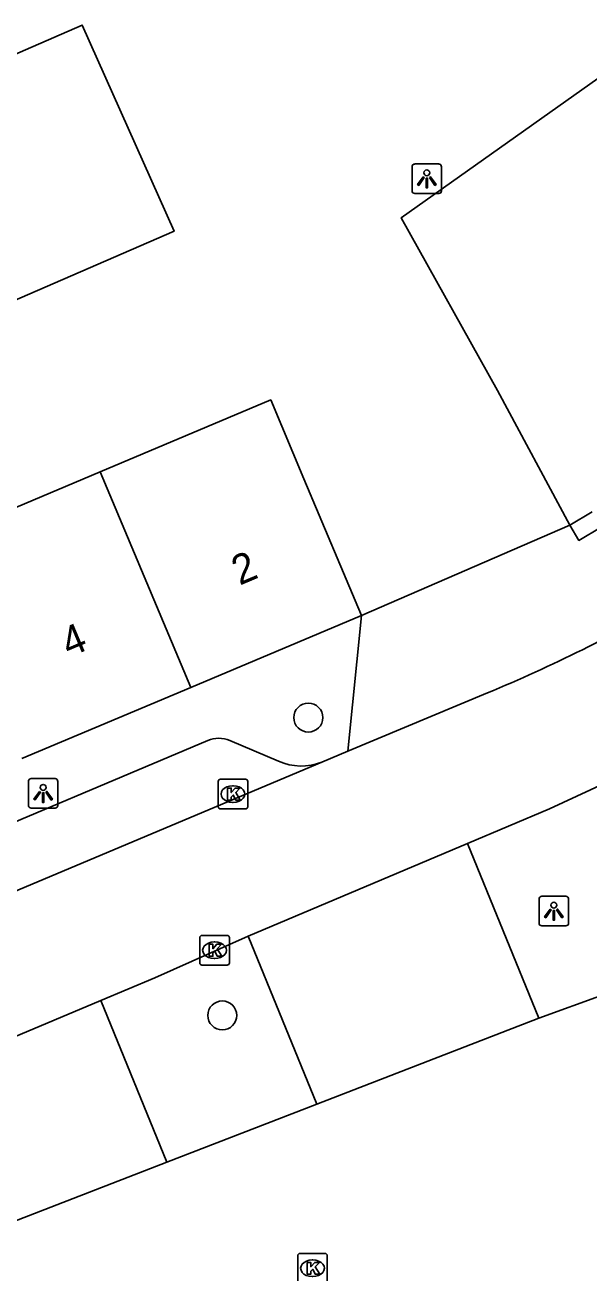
# Model space of a CAD drawing. Extents: x 159888 to 160757, y 384031 to 384746.
# Drawn here: x 160410.46 to 160429.51, y 384536.72 to 384579.11 of the extents above; entities that cross this region are included whole.
import ezdxf

# ---------------------------------------------------------------- set-up
doc = ezdxf.new("R2010")
doc.units = 0
for name, color, linetype in [('IMGEO_Boom', 7, 'Continuous'), ('IMGEO_Kolk', 7, 'Continuous'), ('IMGEO_Lichtpunt', 7, 'Continuous'), ('IMGEO_Pand', 7, 'Continuous'), ('IMGEO_Pand_nummerreeks', 7, 'Continuous'), ('IMGEO_Rijbaan_lokaal_open', 7, 'Continuous'), ('IMGEO_Voetpad_open', 7, 'Continuous')]:
    doc.layers.add(name, color=color, linetype=linetype)

msp = doc.modelspace()

# ---------------------------------------------------------------- linework, layer by layer
at = {"layer": 'IMGEO_Boom'}
for centre in [(160420.029, 384555.732), (160417.123, 384545.68)]:
    msp.add_circle(centre, 0.489, dxfattribs=at)
at = {"layer": 'IMGEO_Kolk'}
for p, q in [((160416.982, 384552.724), (160416.982, 384553.576)), ((160417.057, 384553.65), (160417.909, 384553.65)), ((160417.47, 384553.43), (160417.495, 384553.43)), ((160417.983, 384553.576), (160417.983, 384552.724)), ((160417.909, 384552.65), (160417.057, 384552.65)), ((160417.493, 384552.87), (160417.468, 384552.87)), ((160416.359, 384547.452), (160416.359, 384548.304)), ((160416.434, 384548.378), (160417.286, 384548.378)), ((160417.36, 384548.304), (160417.36, 384547.452)), ((160416.847, 384548.158), (160416.872, 384548.158)), ((160416.87, 384547.598), (160416.845, 384547.598)), ((160417.286, 384547.378), (160416.434, 384547.378)), ((160419.744, 384537.643), (160420.596, 384537.643)), ((160419.669, 384536.717), (160419.669, 384537.569)), ((160420.157, 384537.423), (160420.182, 384537.423)), ((160420.67, 384537.569), (160420.67, 384536.717)), ((160420.18, 384536.863), (160420.155, 384536.863))]:
    msp.add_line(p, q, dxfattribs=at)
for points in [[(160416.982, 384552.724), (160416.982, 384553.576)], [(160417.057, 384553.65), (160417.909, 384553.65)], [(160417.303, 384553.35), (160417.426, 384553.35), (160417.426, 384553.199), (160417.556, 384553.35), (160417.72, 384553.35), (160417.574, 384553.199), (160417.727, 384552.95), (160417.575, 384552.95), (160417.49, 384553.114), (160417.426, 384553.047), (160417.426, 384552.95), (160417.303, 384552.95), (160417.303, 384553.35)], [(160417.983, 384553.576), (160417.983, 384552.724)], [(160417.909, 384552.65), (160417.057, 384552.65)], [(160416.359, 384547.452), (160416.359, 384548.304)], [(160416.434, 384548.378), (160417.286, 384548.378)], [(160417.36, 384548.304), (160417.36, 384547.452)], [(160416.68, 384548.078), (160416.803, 384548.078), (160416.803, 384547.927), (160416.933, 384548.078), (160417.097, 384548.078), (160416.951, 384547.927), (160417.104, 384547.678), (160416.952, 384547.678), (160416.867, 384547.842), (160416.803, 384547.775), (160416.803, 384547.678), (160416.68, 384547.678), (160416.68, 384548.078)], [(160417.286, 384547.378), (160416.434, 384547.378)], [(160419.744, 384537.643), (160420.596, 384537.643)], [(160419.669, 384536.717), (160419.669, 384537.569)], [(160419.99, 384537.343), (160420.113, 384537.343), (160420.113, 384537.192), (160420.243, 384537.343), (160420.407, 384537.343), (160420.261, 384537.192), (160420.414, 384536.943), (160420.262, 384536.943), (160420.177, 384537.107), (160420.113, 384537.04), (160420.113, 384536.943), (160419.99, 384536.943), (160419.99, 384537.343)], [(160420.67, 384537.569), (160420.67, 384536.717)]]:
    msp.add_lwpolyline(points, dxfattribs=at)
for centre, start, end in [((160417.059, 384553.574), 91.552, 178.448), ((160417.059, 384553.574), 91.552, 178.448), ((160417.907, 384553.574), 1.552, 88.448), ((160417.907, 384553.574), 1.552, 88.448), ((160417.059, 384552.726), 181.552, 268.448), ((160417.059, 384552.726), 181.552, 268.448), ((160417.907, 384552.726), 271.552, 358.448), ((160417.907, 384552.726), 271.552, 358.448), ((160416.436, 384548.302), 91.552, 178.448), ((160416.436, 384548.302), 91.552, 178.448), ((160417.284, 384548.302), 1.552, 88.448), ((160417.284, 384548.302), 1.552, 88.448), ((160416.436, 384547.454), 181.552, 268.448), ((160416.436, 384547.454), 181.552, 268.448), ((160417.284, 384547.454), 271.552, 358.448), ((160417.284, 384547.454), 271.552, 358.448), ((160419.746, 384537.567), 91.552, 178.448), ((160419.746, 384537.567), 91.552, 178.448), ((160420.594, 384537.567), 1.552, 88.448), ((160420.594, 384537.567), 1.552, 88.448)]:
    msp.add_arc(centre, 0.0765, start, end, dxfattribs=at)
for centre, major_axis, ratio, start_param, end_param in [((160417.469, 384553.15), (-0.387, 0.002), 0.722429, 4.712389, 7.853982), ((160417.494, 384553.15), (-0.39, 0.002), 0.717154, 1.570796, 4.712389), ((160416.846, 384547.878), (-0.387, 0.002), 0.722429, 4.712389, 7.853982), ((160416.871, 384547.878), (-0.39, 0.002), 0.717154, 1.570796, 4.712389), ((160420.156, 384537.143), (-0.387, 0.002), 0.722429, 4.712389, 7.853982), ((160420.181, 384537.143), (-0.39, 0.002), 0.717154, 1.570796, 4.712389)]:
    msp.add_ellipse(centre, major_axis=major_axis, ratio=ratio, start_param=start_param, end_param=end_param, dxfattribs=at)
at = {"layer": 'IMGEO_Lichtpunt'}
for p, q in [((160423.532, 384574.325), (160423.532, 384573.518)), ((160423.532, 384574.325), (160423.532, 384573.518)), ((160424.434, 384574.42), (160423.626, 384574.42)), ((160424.434, 384574.42), (160423.626, 384574.42)), ((160424.528, 384573.518), (160424.528, 384574.325)), ((160424.528, 384573.518), (160424.528, 384574.325)), ((160423.626, 384573.424), (160424.434, 384573.424)), ((160423.626, 384573.424), (160424.434, 384573.424)), ((160410.571, 384553.577), (160410.571, 384552.77)), ((160410.571, 384553.577), (160410.571, 384552.77)), ((160411.473, 384553.672), (160410.665, 384553.672)), ((160411.473, 384553.672), (160410.665, 384553.672)), ((160411.567, 384552.77), (160411.567, 384553.577)), ((160411.567, 384552.77), (160411.567, 384553.577)), ((160410.665, 384552.676), (160411.473, 384552.676)), ((160410.665, 384552.676), (160411.473, 384552.676)), ((160427.824, 384549.604), (160427.824, 384548.797)), ((160427.824, 384549.604), (160427.824, 384548.797)), ((160428.726, 384549.699), (160427.918, 384549.699)), ((160428.726, 384549.699), (160427.918, 384549.699)), ((160428.82, 384548.797), (160428.82, 384549.604)), ((160428.82, 384548.797), (160428.82, 384549.604)), ((160427.918, 384548.703), (160428.726, 384548.703)), ((160427.918, 384548.703), (160428.726, 384548.703))]:
    msp.add_line(p, q, dxfattribs=at)
for points in [[(160423.906, 384573.989), (160423.945, 384573.961), (160423.757, 384573.699), (160423.719, 384573.726), (160423.906, 384573.989)], [(160424.008, 384573.941), (160424.055, 384573.941), (160424.055, 384573.619), (160424.008, 384573.619), (160424.008, 384573.941)], [(160424.118, 384573.961), (160424.156, 384573.988), (160424.343, 384573.726), (160424.304, 384573.698), (160424.118, 384573.961)], [(160410.945, 384553.241), (160410.984, 384553.213), (160410.796, 384552.951), (160410.758, 384552.978), (160410.945, 384553.241)], [(160411.047, 384553.193), (160411.094, 384553.193), (160411.094, 384552.871), (160411.047, 384552.871), (160411.047, 384553.193)], [(160411.157, 384553.213), (160411.195, 384553.24), (160411.382, 384552.978), (160411.343, 384552.95), (160411.157, 384553.213)], [(160428.198, 384549.268), (160428.237, 384549.24), (160428.049, 384548.978), (160428.011, 384549.005), (160428.198, 384549.268)], [(160428.3, 384549.22), (160428.347, 384549.22), (160428.347, 384548.898), (160428.3, 384548.898), (160428.3, 384549.22)], [(160428.41, 384549.24), (160428.448, 384549.267), (160428.635, 384549.005), (160428.596, 384548.977), (160428.41, 384549.24)]]:
    msp.add_lwpolyline(points, dxfattribs=at)
for centre in [(160424.031, 384574.123), (160411.07, 384553.375), (160428.323, 384549.402)]:
    msp.add_circle(centre, 0.0994, dxfattribs=at)
for centre, start, end in [((160423.626, 384574.325), 90, 180), ((160423.626, 384574.325), 90, 180), ((160424.434, 384574.325), 0, 90), ((160424.434, 384574.325), 0, 90), ((160423.626, 384573.518), 180, 270), ((160423.626, 384573.518), 180, 270), ((160424.434, 384573.518), 270, 0), ((160424.434, 384573.518), 270, 360), ((160410.665, 384553.577), 90, 180), ((160410.665, 384553.577), 90, 180), ((160411.473, 384553.577), 0, 90), ((160411.473, 384553.577), 0, 90), ((160410.665, 384552.77), 180, 270), ((160410.665, 384552.77), 180, 270), ((160411.473, 384552.77), 270, 0), ((160411.473, 384552.77), 270, 360), ((160427.918, 384549.604), 90, 180), ((160427.918, 384549.604), 90, 180), ((160428.726, 384549.604), 0, 90), ((160428.726, 384549.604), 0, 90), ((160427.918, 384548.797), 180, 270), ((160427.918, 384548.797), 180, 270), ((160428.726, 384548.797), 270, 0), ((160428.726, 384548.797), 270, 360)]:
    msp.add_arc(centre, 0.0946, start, end, dxfattribs=at)
at = {"layer": 'IMGEO_Pand'}
for points in [[(160401.843, 384574.522), (160412.389, 384579.108), (160415.493, 384572.149), (160404.798, 384567.512)], [(160432.047, 384578.89), (160423.166, 384572.604), (160426.417, 384566.77), (160428.859, 384562.226)], [(160412.991, 384564.023), (160418.759, 384566.454), (160419.881, 384563.791), (160421.823, 384559.183)], [(160407.283, 384561.617), (160412.991, 384564.023)], [(160412.991, 384564.023), (160416.055, 384556.752)], [(160428.859, 384562.226), (160429.614, 384562.681)], [(160421.823, 384559.183), (160416.055, 384556.752)], [(160416.055, 384556.752), (160410.349, 384554.348)]]:
    msp.add_lwpolyline(points, dxfattribs=at)
at = {"layer": 'IMGEO_Rijbaan_lokaal_open'}
for points in [[(160436.506, 384557.107), (160435.452, 384556.441), (160433.566, 384555.285), (160431.872, 384554.363), (160428.176, 384552.657), (160425.402, 384551.486)], [(160426.08, 384556.566), (160421.369, 384554.595)], [(160421.369, 384554.595), (160420.485, 384554.23)], [(160420.485, 384554.23), (160405.149, 384547.777)], [(160417.992, 384548.357), (160425.402, 384551.486)], [(160413.022, 384546.183), (160414.841, 384546.947), (160417.992, 384548.357)], [(160405.552, 384543.044), (160413.022, 384546.183)]]:
    msp.add_lwpolyline(points, dxfattribs=at)
msp.add_arc((160405.714, 384605.651), 53.143, 292.534, 300.1303, dxfattribs=at)
at = {"layer": 'IMGEO_Voetpad_open'}
for points in [[(160428.859, 384562.226), (160421.823, 384559.183)], [(160429.927, 384562.164), (160429.173, 384561.715), (160428.859, 384562.226)], [(160421.369, 384554.595), (160421.823, 384559.183)], [(160407.394, 384551.064), (160416.63, 384554.96)], [(160417.375, 384554.961), (160419.019, 384554.258)], [(160425.402, 384551.486), (160427.82, 384545.58)], [(160417.992, 384548.357), (160420.318, 384542.688)], [(160427.82, 384545.58), (160429.994, 384546.375), (160433.002, 384548.194)], [(160413.022, 384546.183), (160415.244, 384540.729)], [(160427.82, 384545.58), (160420.318, 384542.688)], [(160420.318, 384542.688), (160415.244, 384540.729)], [(160415.244, 384540.729), (160407.602, 384537.77)]]:
    msp.add_lwpolyline(points, dxfattribs=at)
for centre, radius, start, end in [((160417.004, 384554.053), 0.981, 67.7528, 112.401), ((160419.785, 384555.985), 1.889, 246.0751, 291.7365)]:
    msp.add_arc(centre, radius, start, end, dxfattribs=at)

# ---------------------------------------------------------------- texts
at = {"layer": 'IMGEO_Pand_nummerreeks'}
for s, p in [('2', (160417.706, 384560.183)), ('4', (160411.944, 384557.754))]:
    msp.add_text(s, height=1, rotation=22.8514, dxfattribs=at).set_placement(p)

doc.saveas('drawing.dxf')
